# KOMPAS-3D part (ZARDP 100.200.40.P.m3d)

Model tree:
1. Операция без истории:1
2. Операция без истории:2
3. Операция без истории:3
4. Операция без истории:4
5. Операция без истории:5
6. Операция без истории:6
7. Операция без истории:7
8. Операция без истории:8
9. Операция без истории:9
10. Операция без истории:10
11. Операция без истории:11
12. Операция без истории:12
13. Операция без истории:13
14. Операция без истории:14
15. Операция без истории:15
16. Операция без истории:16
17. Операция без истории:17
18. Операция без истории:18
19. Операция без истории:19
20. Операция без истории:20
21. Операция без истории:21
22. Операция без истории:22
23. Операция без истории:23
24. Операция без истории:24
25. Операция без истории:25
26. Операция без истории:26
27. Операция без истории:27
28. Операция без истории:28
29. Операция без истории:29
30. Операция без истории:30
31. Операция без истории:31
32. Операция без истории:32
33. Операция без истории:33
34. Операция без истории:34
35. Операция без истории:35
36. Операция без истории:36
37. Операция без истории:37
38. Операция без истории:38
39. Операция без истории:39
40. Операция без истории:40
41. Операция без истории:41
42. Операция без истории:42
43. Операция без истории:43
44. Операция без истории:44
45. Операция без истории:45
46. Операция без истории:46
47. Операция без истории:47
48. Операция без истории:48
49. Операция без истории:49
50. Операция без истории:50
51. Операция без истории:51
52. Операция без истории:52
53. Операция без истории:53
54. Операция без истории:54
55. Операция без истории:55
56. Операция без истории:56
57. Операция без истории:57
58. Операция без истории:58
59. Операция без истории:59
60. Операция без истории:60
61. Операция без истории:61
62. Операция без истории:62
63. Операция без истории:63
64. Операция без истории:64
65. Операция без истории:65
66. Операция без истории:66
67. Операция без истории:67
68. Операция без истории:68
69. Операция без истории:69
70. Операция без истории:70
71. Операция без истории:71
72. Операция без истории:72
73. Операция без истории:73
74. Операция без истории:74
75. Операция без истории:75
76. Операция без истории:76
77. Поверхность без истории:1

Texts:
  ЗАРДП 100.250.40-ХХ.Р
